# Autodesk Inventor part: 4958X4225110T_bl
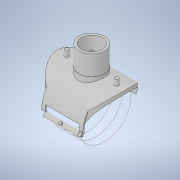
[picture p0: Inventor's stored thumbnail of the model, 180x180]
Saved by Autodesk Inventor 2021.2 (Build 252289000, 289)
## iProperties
Created: 2020-06
Part Number: 4958X4225110T_bl
Material: Generic
Description: Plasson Branch Saddle 225x110
Document SubType Name: Modeling
Designer: KIM
Density: 1 g/cm^3
Appearance: Default
Author: KIM
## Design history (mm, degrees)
derived "4958X4.ipt"
feature "Solid1::4958X4.ipt" dims "ScaleForDerivedMember" = 10
tag "TaggingFeature1"
body "Solid1"
other parameters: "d0" = 295 [user parameter], "d2" = 225 [user parameter], "d3" = 253.2 [user parameter], "d4" = 112 [user parameter], "d7" = 89 [user parameter], "d9" = 85 [user parameter], "d10" = 0.5 [user parameter], "d11" = 1 [user parameter], "d12" = 28 [user parameter], "d13" = 16 [user parameter], "d14" = 8 [user parameter], "d16" = 10 deg [user parameter], "d17" = 10 deg [user parameter], "d19" = 0 [user parameter], "d23" = 0 [user parameter], "d26" = 0 [user parameter], "d27" = 177 [user parameter], "d28" = 0 [user parameter], "d29" = 147.5 [user parameter], "d30" = 0 [user parameter], "d31" = 1 [user parameter], "d32" = 1 [user parameter], "d33" = 19.2 [user parameter], "d34" = 9.6 [user parameter], "d35" = 45 deg [user parameter], "d36" = 147.5 [user parameter], "d37" = 0 [user parameter], "d38" = 5 [user parameter], "d39" = 85 deg [user parameter], "d40" = 28 [user parameter], "d41" = 16 [user parameter], "d42" = 107.27273 [user parameter], "d49" = 3 [user parameter], "d50" = 6 [user parameter], "d51" = 5 [user parameter], "d54" = 0 [user parameter], "d57" = 35 deg [user parameter], "d60" = 18.4375 [user parameter], "d61" = 1 [user parameter], "d62" = 90 deg [user parameter], "d63" = 2 [user parameter], "d64" = 0 [user parameter], "d65" = 0 [user parameter], "d68" = 36.875 [user parameter], "d70" = 0.57711 [user parameter], "d71" = 10 deg [user parameter], "d73" = 4.935 [user parameter], "d" = 225 [user parameter], "B" = 272 [user parameter], "L" = 295 [user parameter], "LS" = 85 [user parameter], "H1" = 112 [user parameter], "Dt" = 16 [user parameter], "di" = 89 [user parameter], "d72" = 14.1 [user parameter]
